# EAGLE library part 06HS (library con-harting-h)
CONNECTOR
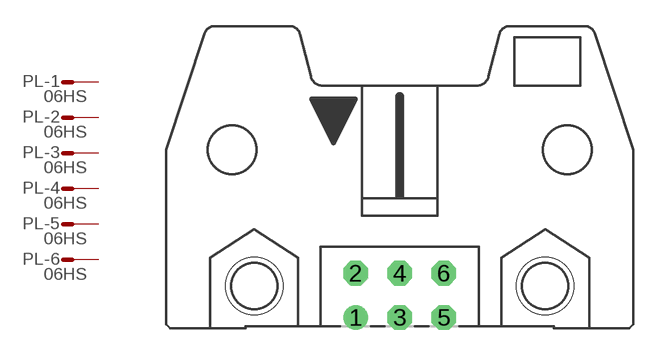
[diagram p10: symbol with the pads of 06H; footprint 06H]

Designator prefix PL; gates -1=M -2=M -3=M -4=M -5=M -6=M

## 06HS (OC_FARNELL: unknown; OC_NEWARK: unknown)  [06H]
1  -1:S  pas
2  -2:S  pas
3  -3:S  pas
4  -4:S  pas
5  -5:S  pas
6  -6:S  pas

## Footprint 06H (pad centres in mm)
CONNECTOR
drill 0.914 round: 1 -2.54,-1.27
drill 0.914 octagon: 2 -2.54,1.27; 3 0,-1.27; 4 0,1.27; 5 2.54,-1.27; 6 2.54,1.27
hole 3.302 at -8.382,0.533
hole 3.302 at 8.382,0.533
